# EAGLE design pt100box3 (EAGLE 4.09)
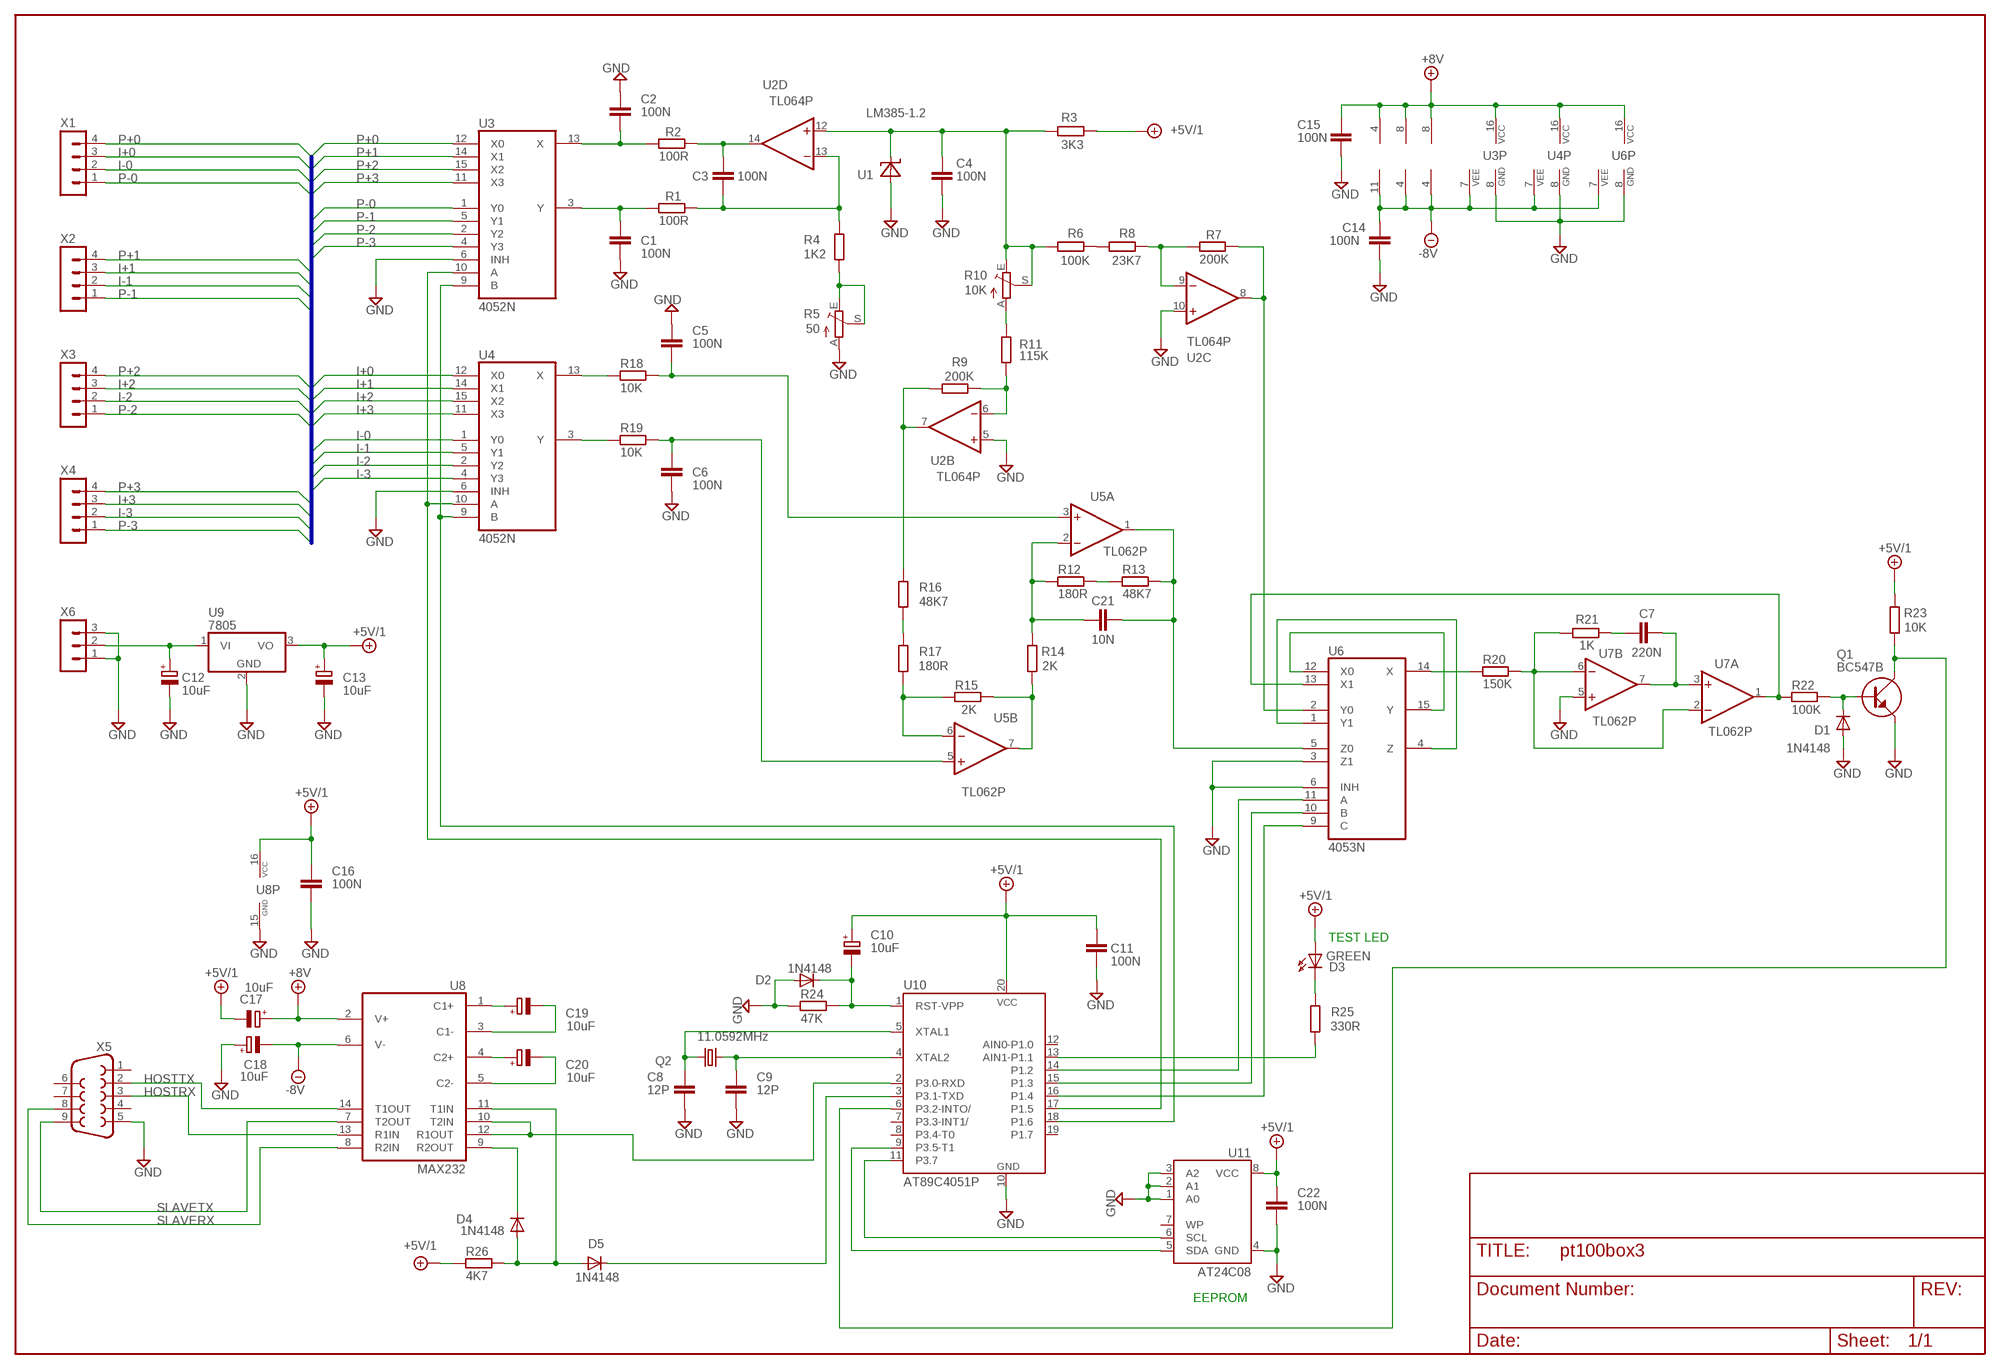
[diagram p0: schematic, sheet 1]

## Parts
C1  100N  NEWCC5  [C5]
C2  100N  NEWCC5  [C5]
C3  100N  NEWCC5  [C5]
C4  100N  NEWCC5  [C5]
C5  100N  NEWCC5  [C5]
C6  100N  NEWCC5  [C5]
C7  220N  C-EU102-064X133  [C102-064X133]
C8  12P  NEWCC2.5  [C2.5]
C9  12P  NEWCC2.5  [C2.5]
C10  10uF  CPOL-EUE2.5-6  [E2,5-6]
C11  100N  NEWCC5  [C5]
C12  10uF  CPOL-EUE2.5-6  [E2,5-6]
C13  10uF  CPOL-EUE2.5-6  [E2,5-6]
C14  100N  NEWCC5  [C5]
C15  100N  NEWCC5  [C5]
C16  100N  NEWCC5  [C5]
C17  10uF  CPOL-EUE2.5-6  [E2,5-6]
C18  10uF  CPOL-EUE2.5-6  [E2,5-6]
C19  10uF  CPOL-EUE2.5-6  [E2,5-6]
C20  10uF  CPOL-EUE2.5-6  [E2,5-6]
C21  10N  NEWCC2.5  [C2.5]
C22  100N  NEWC0805  [0805]
D1  1N4148  NEWDD7.5  [D7.5]
D2  1N4148  NEWDD7.5  [D7.5]
D3  GREEN  LED3MM  [LED3MM]
D4  1N4148  NEWDD7.5  [D7.5]
D5  1N4148  NEWDD7.5  [D7.5]
Q1  BC547B  NPNTO92  [TO92]
Q2  11.0592MHz  HC18U-V  [HC18U-V]
R1  100R  NEWRRM10  [RM10]
R2  100R  NEWRRM10  [RM10]
R3  3K3  NEWRRM10  [RM10]
R4  1K2  NEWRRM10  [RM10]
R5  50  TRIM_EU-S64Y  [S64Y]
R6  100K  NEWRRM10  [RM10]
R7  200K  NEWRRM10  [RM10]
R8  23K7  NEWRRM10  [RM10]
R9  200K  NEWRRM10  [RM10]
R10  10K  TRIM_EU-S64Y  [S64Y]
R11  115K  NEWRRM10  [RM10]
R12  180R  NEWRRM10  [RM10]
R13  48K7  NEWRRM10  [RM10]
R14  2K  NEWRRM10  [RM10]
R15  2K  NEWRRM10  [RM10]
R16  48K7  NEWRRM10  [RM10]
R17  180R  NEWRRM10  [RM10]
R18  10K  NEWRRM10  [RM10]
R19  10K  NEWRRM10  [RM10]
R20  150K  NEWRRM10  [RM10]
R21  1K  NEWRRM10  [RM10]
R22  100K  NEWRRM10  [RM10]
R23  10K  NEWRRM10  [RM10]
R24  47K  NEWRRM10  [RM10]
R25  330R  NEWRRM10  [RM10]
R26  4K7  NEWRRM10  [RM10]
U1  LM385-1.2  LM385TO  [TO92]
U2  TL064P  TL084P  [DIL14]
U3  4052N  [DIL16]
U4  4052N  [DIL16]
U5  TL062P  TL082P  [DIL08]
U6  4053N  [DIL16]
U7  TL062P  TL082P  [DIL08]
U8  MAX232  [DIL16]
U9  7805  78V  [TO220V]
U10  AT89C4051P  AT89C2051P  [DIL20]
U11  AT24C08  AT24CSO  [SOIC-8]
X1  MA04-1  [MA04-1]
X2  MA04-1  [MA04-1]
X3  MA04-1  [MA04-1]
X4  MA04-1  [MA04-1]
X5  F09H  [F09H]
X6  MA03-1  [MA03-1]

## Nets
+1.2: C4.2 R3.2 R6.2 R10.E R10.S U1.B(C) U2.12(D:+IN)
+5V/1: C10.+ C11.2 C13.+ C16.2 C17.- C22.2 D3.A R3.1 R23.2 R26.1 U8.16(VCC) U9.3(VO) U10.20(VCC) U11.8(VCC)
+8V: C15.2 C17.+ U2.4(P:V+) U3.16(VCC) U4.16(VCC) U5.8(P:V+) U6.16(VCC) U7.8(P:V+) U8.2(V+)
+12V: C12.+ U9.1(VI) X6.2
-2V: R7.2 U2.8(C:OUT) U6.2(Y0)
-8V: C14.2 C18.- U2.11(P:V-) U3.7(VEE) U4.7(VEE) U5.4(P:V-) U6.7(VEE) U7.4(P:V-) U8.6(V-)
-OFF: R9.2 R16.2 U2.7(B:OUT)
A: U6.11(A) U10.14(P1.2)
B: U6.10(B) U10.15(P1.3)
C: U6.9(C) U10.16(P1.4)
C1+: C19.+ U8.1(C1+)
C1-: C19.- U8.3(C1-)
C2+: C20.+ U8.4(C2+)
C2-: C20.- U8.5(C2-)
GND: C1.1 C2.2 C4.1 C5.2 C6.1 C8.1 C9.1 C11.1 C12.- C13.- C14.1 C15.1 C16.1 C18.+ C22.1 D1.A D2.A Q1.E R5.A R24.1 U1.E(A) U2.5(B:+IN) U2.10(C:+IN) U3.6(INH) U3.8(GND) U4.6(INH) U4.8(GND) U6.3(Z1) U6.6(INH) U6.8(GND) U7.5(B:+IN) U8.15(GND) U9.2(GND) U10.10(GND) U11.1(A0) U11.2(A1) U11.3(A2) U11.4(GND) X5.5 X6.1 X6.3
HOSTRX: U8.13(R1IN) X5.3
HOSTTX: U8.14(T1OUT) X5.2
I+0: U4.12(X0) X1.3
I+1: U4.14(X1) X2.3
I+2: U4.15(X2) X3.3
I+3: U4.11(X3) X4.3
I-0: U4.1(Y0) X1.2
I-1: U4.5(Y1) X2.2
I-2: U4.2(Y2) X3.2
I-3: U4.4(Y3) X4.2
INT0: Q1.C R23.1 U10.6(P3.2-INTO/)
LED1: R25.1 U10.13(AIN1-P1.1)
LED2: D3.K(C) R25.2
N$1: D4.C U8.9(R2OUT)
N$2: D4.A D5.A R26.2 U8.11(T1IN)
N$8: U10.9(P3.5-T1) U11.5(SDA)
N$9: U10.11(P3.7) U11.6(SCL)
P+0: U3.12(X0) X1.4
P+1: U3.14(X1) X2.4
P+2: U3.15(X2) X3.4
P+3: U3.11(X3) X4.4
P-0: U3.1(Y0) X1.1
P-1: U3.5(Y1) X2.1
P-2: U3.2(Y2) X3.1
P-3: U3.4(Y3) X4.1
Q1: C8.2 Q2.2 U10.5(XTAL1)
Q2: C9.2 Q2.1 U10.4(XTAL2)
RESET: C10.- D2.C R24.2 U10.1(RST-VPP)
RXD: U8.10(T2IN) U8.12(R1OUT) U10.2(P3.0-RXD)
SELA: U3.10(A) U4.10(A) U10.17(P1.5)
SELB: U3.9(B) U4.9(B) U10.18(P1.6)
SLAVERX: U8.8(R2IN) X5.8
SLAVETX: U8.7(T2OUT) X5.9
TXD: D5.C U10.3(P3.1-TXD)
X1: C2.1 R2.1 U3.13(X)
X2: C1.2 R1.1 U3.3(Y)
X3: C3.2 R2.2 U2.14(D:OUT)
X4: C3.1 R1.2 R4.2 U2.13(D:-IN)
X5: R4.1 R5.E R5.S
X6: R6.1 R8.2
X7: R7.1 R8.1 U2.9(C:-IN)
X8: R10.A R11.1
X9: R9.1 R11.2 U2.6(B:-IN)
X10: R18.1 U4.13(X)
X11: R19.1 U4.3(Y)
X12: C5.1 R18.2 U5.3(A:+IN)
X13: C6.2 R19.2 U5.5(B:+IN)
X14: R16.1 R17.2
X15: R15.1 R17.1 U5.6(B:-IN)
X16: R14.1 R15.2 U5.7(B:OUT)
X17: C21.2 R12.1 R14.2 U5.2(A:-IN)
X18: R12.2 R13.1
X19: C21.1 R13.2 U5.1(A:OUT) U6.5(Z0)
X20: R20.1 U6.14(X)
X21: R20.2 R21.1 U7.2(A:-IN) U7.6(B:-IN)
X22: C7.1 R21.2
X23: C7.2 U7.3(A:+IN) U7.7(B:OUT)
X24: R22.1 U6.13(X1) U7.1(A:OUT)
X25: D1.C Q1.B R22.2
X26: U6.1(Y1) U6.4(Z)
X27: U6.12(X0) U6.15(Y)
Unconnected: U2.1(A:OUT) U2.2(A:-IN) U2.3(A:+IN) U10.7(P3.3-INT1/) U10.8(P3.4-T0) U10.12(AIN0-P1.0) U10.19(P1.7) U11.7(WP) X5.1 X5.4 X5.6 X5.7

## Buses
P+[0..3],P-[0..3],I+[0..3],I-[0..3]

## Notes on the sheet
- TEST LED
- EEPROM

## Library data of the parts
C1-C6 C8 C9 C11 C14-C16 C21 C22 = NEWRC:NEWC
C7 = rcl:C-EU: CAPACITOR, European symbol
C10 C12 C13 C17-C20 = rcl:CPOL-EU: POLARIZED CAPACITOR, European symbol
D1 D2 D4 D5 = NEWRC:NEWD
D3 = led:LED3MM: LED
Q1 = NEWRC:NPN
Q2 = crystal:HC18U-V: CRYSTAL
R1-R4 R6-R9 R11-R26 = NEWRC:NEWR
R5 R10 = pot:TRIM_EU-: POTENTIOMETER
U1 = NEWRC:LM385
U2 = linear:TL084: OP AMP
U3 U4 = 40xx:4052: Dual 4-channel ANALOG MULTIPLEXER
U5 U7 = linear:TL082: OP AMP
U6 = 40xx:4053: Triple 2-channel ANALOG MULTIPLEXER
U8 = maxim:MAX232: RS232 TRANSEIVER
U9 = linear:78*: Positive VOLTAGE REGULATOR
U10 = atmel:AT89C2051: 80C31 MICROCONTROLLER 2 Kbytes FLASH 2.7 V
U11 = atmel:AT24C*: 2-wire serial EEPROM
X1-X4 = con-lstb:MA04-1: PIN HEADER
X5 = con-subd:F09: SUB-D
X6 = con-lstb:MA03-1: PIN HEADER

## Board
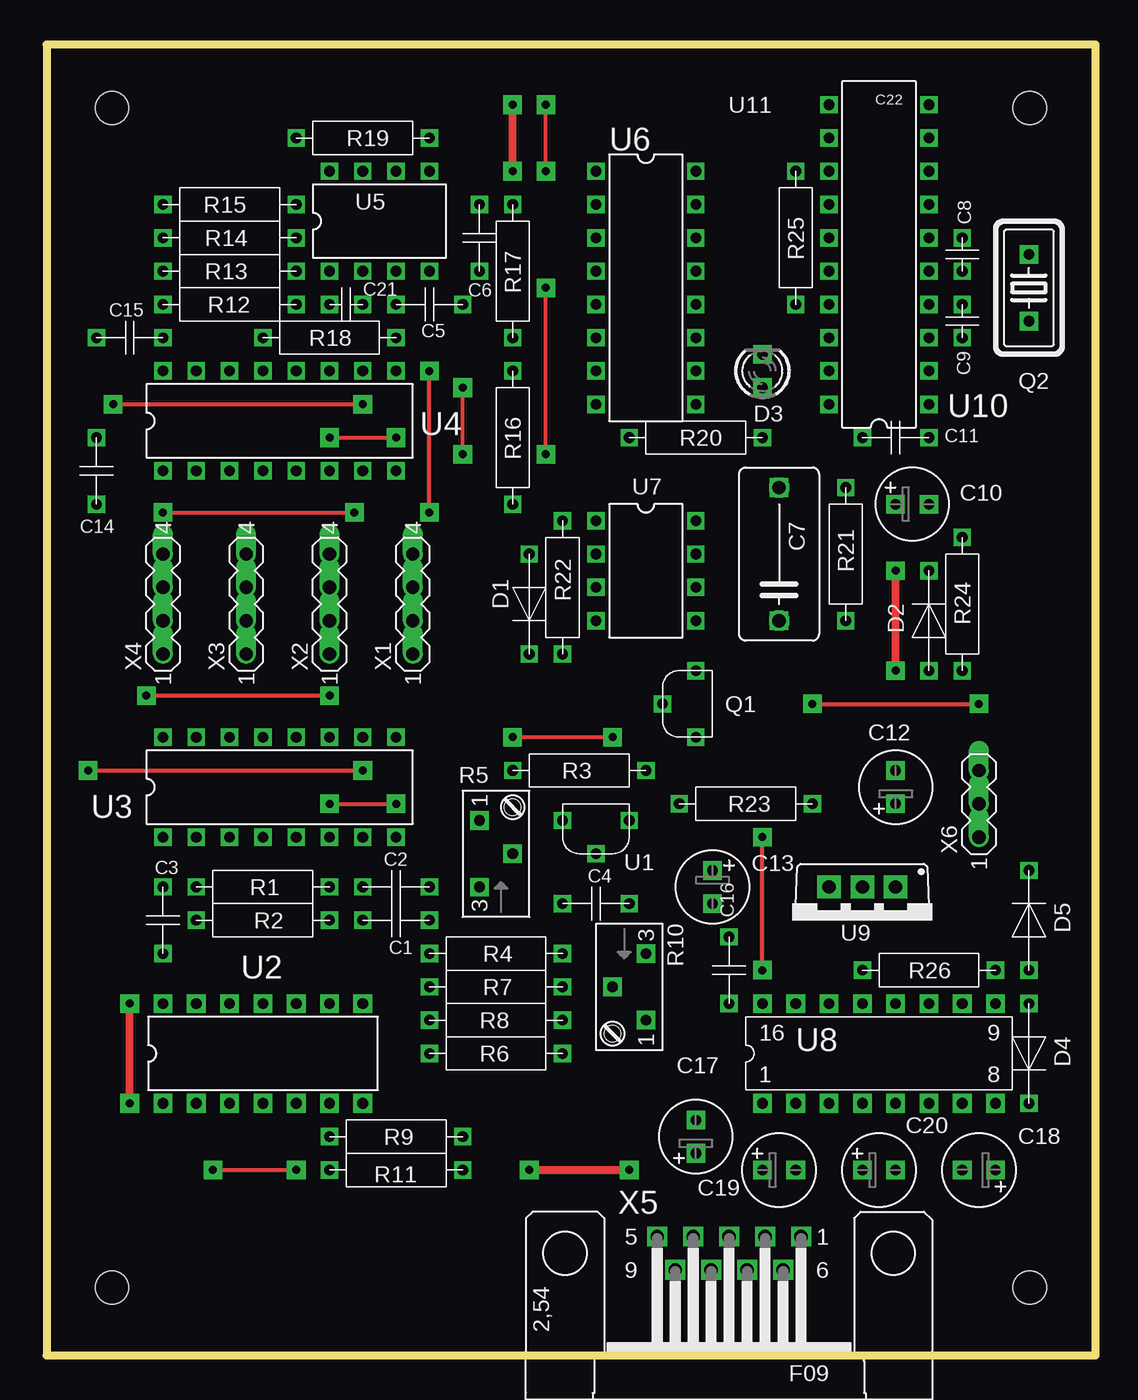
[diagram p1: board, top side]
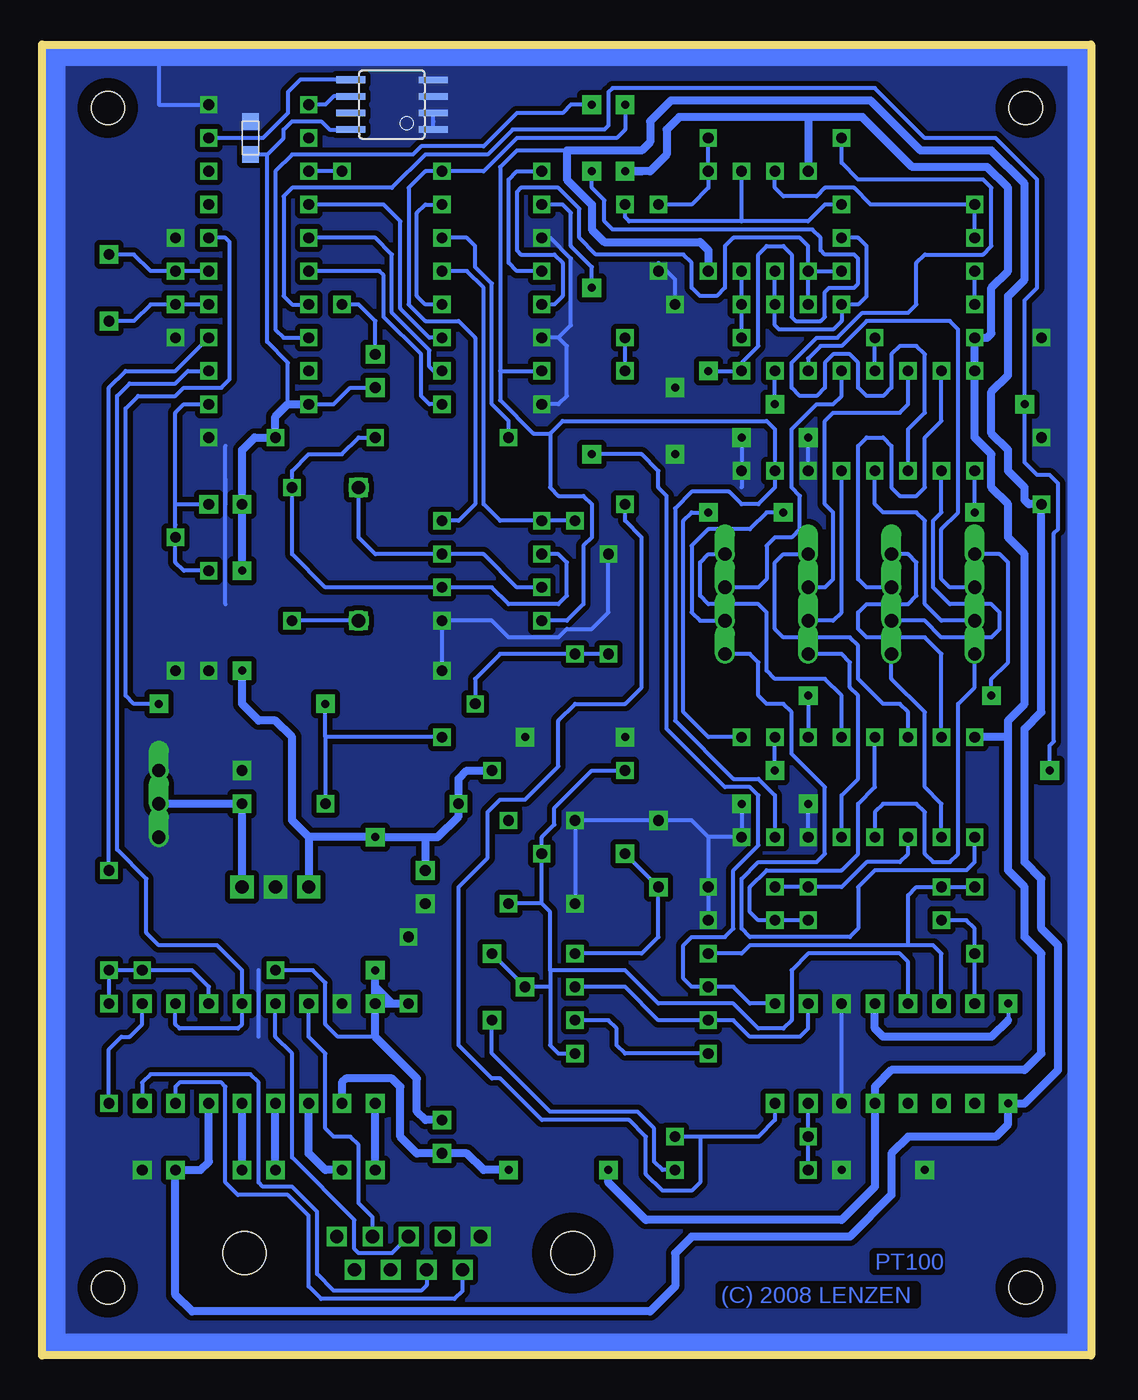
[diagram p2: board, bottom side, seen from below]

Size 80 x 100 mm. Coordinates in mm from the lower left corner, seen from the top.
Outline: 0,0 80,0 80,100 0,100 0,0
Copper layers used: Top, Bottom
Holes 2.54 mm at 4.98,95.17 74.98,95.17 74.98,5.17 4.98,5.17

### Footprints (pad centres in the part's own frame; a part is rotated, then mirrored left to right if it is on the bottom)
C5 = drill 0.813 pad 1.27 square: 1 0,0; 2 5.08,0
C102-064X133 = drill 1.016 octagon: 1 -5.08,0; 2 5.08,0
C2.5 = drill 0.813 pad 1.27 square: 1 0,0; 2 2.54,0
E2,5-6 = drill 0.813 pad 1.422 square: + -1.27,0; - 1.27,0
0805 = smd 1.27 x 1.27: 1 0,0; 2 2.54,0
D7.5 = drill 0.813 pad 1.27 square: A 0,0; C 7.62,0
LED3MM = drill 0.813 octagon: A -1.27,0; K 1.27,0
TO92 = drill 0.813 pad 1.27 square: B 0,0; C 2.54,-2.54; E 2.54,2.54
HC18U-V = drill 0.813 pad 1.422 square: 1 -2.54,0; 2 2.54,0
RM10 = drill 0.813 pad 1.27 square: 1 0,0; 2 10.16,0
S64Y = drill 0.813 pad 1.422 square: A 2.54,1.27; E -2.54,1.27; S 0,-1.27
DIL14 = drill 0.813 pad 1.422 square: 1 -7.62,-3.81; 2 -5.08,-3.81; 3 -2.54,-3.81; 4 0,-3.81; 5 2.54,-3.81; 6 5.08,-3.81; 7 7.62,-3.81; 8 7.62,3.81; 9 5.08,3.81; 10 2.54,3.81; 11 0,3.81; 12 -2.54,3.81; 13 -5.08,3.81; 14 -7.62,3.81
DIL16 = drill 0.813 square: 1 -8.89,-3.81; 2 -6.35,-3.81; 3 -3.81,-3.81; 4 -1.27,-3.81; 5 1.27,-3.81; 6 3.81,-3.81; 7 6.35,-3.81; 8 8.89,-3.81; 9 8.89,3.81; 10 6.35,3.81; 11 3.81,3.81; 12 1.27,3.81; 13 -1.27,3.81; 14 -3.81,3.81; 15 -6.35,3.81; 16 -8.89,3.81
DIL08 = drill 0.813 square: 1 -3.81,-3.81; 2 -1.27,-3.81; 3 1.27,-3.81; 4 3.81,-3.81; 5 3.81,3.81; 6 1.27,3.81; 7 -1.27,3.81; 8 -3.81,3.81
DIL16' = drill 0.813 pad 1.422 square: 1 -8.89,-3.81; 2 -6.35,-3.81; 3 -3.81,-3.81; 4 -1.27,-3.81; 5 1.27,-3.81; 6 3.81,-3.81; 7 6.35,-3.81; 8 8.89,-3.81; 9 8.89,3.81; 10 6.35,3.81; 11 3.81,3.81; 12 1.27,3.81; 13 -1.27,3.81; 14 -3.81,3.81; 15 -6.35,3.81; 16 -8.89,3.81
TO220V = drill 1.016 pad 1.778 square: 1 -2.54,0; 2 0,0; 3 2.54,0
DIL20 = drill 0.813 square: 1 -11.43,-3.81; 2 -8.89,-3.81; 3 -6.35,-3.81; 4 -3.81,-3.81; 5 -1.27,-3.81; 6 1.27,-3.81; 7 3.81,-3.81; 8 6.35,-3.81; 9 8.89,-3.81; 10 11.43,-3.81; 11 11.43,3.81; 12 8.89,3.81; 13 6.35,3.81; 14 3.81,3.81; 15 1.27,3.81; 16 -1.27,3.81; 17 -3.81,3.81; 18 -6.35,3.81; 19 -8.89,3.81; 20 -11.43,3.81
SOIC-8 = smd 0.5 x 2.2: 1 -1.905,-3.154; 2 -0.645,-3.154; 3 0.625,-3.154; 4 1.895,-3.154; 5 1.905,3.154; 6 0.635,3.154; 7 -0.635,3.154; 8 -1.905,3.154
MA04-1 = drill 1.016 offset: 1 -3.81,0; 2 -1.27,0; 3 1.27,0; 4 3.81,0
F09H = drill 1.016 pad 1.422 square: 1 -5.486,-1.27; 2 -2.743,-1.27; 3 0,-1.27; 4 2.743,-1.27; 5 5.486,-1.27; 6 -4.115,1.27; 7 -1.372,1.27; 8 1.372,1.27; 9 4.115,1.27 | hole 3.302: -12.522,0; 12.522,0
MA03-1 = drill 1.016 offset: 1 -2.54,0; 2 0,0; 3 2.54,0

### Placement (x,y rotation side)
C1  29.19,35.73 180 top
C2  24.11,33.19 0 top
C3  8.87,35.73 270 top
C4  39.35,34.46 0 top
C5  26.65,80.18 0 top
C6  33,82.72 90 top
C7  55.86,61.13 90 top
C8  69.83,85.26 270 top
C9  69.83,77.64 90 top
C10  66.02,64.94 0 top
C11  67.29,70.02 180 top
C12  64.75,43.35 90 top
C13  50.78,35.73 270 top
C14  3.79,70.02 270 top
C15  3.79,77.64 0 top
C16  52.05,31.92 270 top
C17  49.51,16.68 90 top
C18  71.1,14.14 180 top
C19  55.86,14.14 0 top
C20  63.48,14.14 0 top
C21  21.57,80.18 0 top
C22  64.11,94.15 270 bottom
D1  36.81,61.13 270 top
D2  67.29,52.24 90 top
D3  54.59,75.1 90 top
D4  74.91,26.84 270 top
D5  74.91,29.38 90 top
Q1  46.97,49.7 0 top
Q2  74.91,81.45 90 top
R1  21.57,35.73 180 top
R2  21.57,33.19 180 top
R3  45.7,44.62 180 top
R4  39.35,30.65 180 top
R5  34.27,38.27 90 top
R6  29.19,23.03 0 top
R7  39.35,28.11 180 top
R8  29.19,25.57 0 top
R9  21.57,16.68 0 top
R10  44.43,28.11 270 top
R11  31.73,14.14 180 top
R12  19.03,80.18 180 top
R13  8.87,82.72 0 top
R14  8.87,85.26 0 top
R15  19.03,87.8 180 top
R16  35.54,75.1 270 top
R17  35.54,87.8 270 top
R18  16.49,77.64 0 top
R19  19.03,92.88 0 top
R20  44.43,70.02 0 top
R21  60.94,66.21 270 top
R22  39.35,63.67 270 top
R23  58.4,42.08 180 top
R24  69.83,52.24 90 top
R25  57.13,90.34 270 top
R26  62.21,29.38 0 top
U1  41.89,38.27 90 top
U2  16.49,23.03 0 top
U3  17.76,43.35 0 top
U4  17.76,71.29 0 top
U5  25.38,86.53 0 top
U6  45.7,81.45 270 top
U7  45.7,59.86 270 top
U8  MAX232  [DIL16']  63.48,23.03 0 top
U9  62.21,35.73 180 top
U10  63.48,83.99 90 top
U11  53.32,95.42 90 bottom
X1  27.92,57.32 90 top
X2  21.57,57.32 90 top
X3  15.22,57.32 90 top
X4  8.87,57.32 90 top
X5  52.05,7.79 180 top
X6  71.1,42.08 90 top

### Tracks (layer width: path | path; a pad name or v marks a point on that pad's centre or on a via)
+1.2
  Bottom 0.305: R3.2 38.08,44.62 40.94,41.76 40.94,40.49 41.89,39.54 U1.B 41.89,34.46 | U2.12 13.95,30.02 14.58,30.65 21.57,30.65 22.84,29.38 22.84,25.57 23.47,24.94 25.38,24.94 27.28,26.84 33,26.84 35.54,29.38 41.25,29.38 | 41.25,29.38 41.25,33.83 41.89,34.46 | 41.89,34.46 C4.2 | 41.25,29.38 41.25,28.11 | 41.25,28.11 41.25,23.67 40.62,23.03 R6.2 | R10.E R10.S 41.25,28.11
+5V/1  (via drill 0.61 pad 1.42)
  Top 0.305: v54.59,29.38 v54.59,39.54
  Top 0.61: v64.75,52.24 v64.75,59.86
  Bottom 0.305: U10.20 57.76,72.56 56.49,73.83 D3.A | R26.1 59.35,29.38 58.4,28.43 58.4,25.25 57.45,24.3 54.59,24.3 | U11.8 58.08,93.52 58.71,94.15 60.94,94.15 61.57,93.52 61.57,92.88 62.84,91.61 | 62.84,91.61 62.84,77.32 61.26,75.73 61.26,72.56 | 62.84,91.61 C22.2
  Bottom 0.61: R3.1 47.6,44.62 48.24,43.98 R23.2 48.24,41.13 49.82,39.54 50.78,39.54 | U8.16 53.32,26.84 | 53.32,26.84 C16.2 | C17.- 50.78,17.95 51.41,18.59 51.41,21.12 54.59,24.3 U8.16 | v64.75,59.86 C10.+ 64.75,69.07 63.8,70.02 C11.2 62.21,71.61 61.26,72.56 U10.20 | v64.75,52.24 64.75,49.7 63.48,48.43 62.21,48.43 60.94,47.16 60.94,40.81 59.67,39.54 | 59.67,39.54 v54.59,39.54 50.78,39.54 | 59.67,39.54 U9.3 | 50.78,39.54 C13.+ | U8.16 54.59,28.11 | 54.59,28.11 v54.59,29.38 | 53.32,26.84 54.59,28.11
+8V  (via drill 0.61 pad 1.42)
  Top 0.61: v35.54,90.34 v35.54,95.42 | v36.81,14.14 v44.43,14.14
  Bottom 0.305: U7.8 48.24,63.67 46.97,64.94 46.97,77.64 48.24,78.91 50.78,78.91 52.05,80.18 52.05,89.07 50.78,90.34 U6.16 46.33,90.34 43.79,92.88 36.17,92.88 35.54,93.52 v35.54,95.42
  Bottom 0.61: 6.33,47.16 6.33,48.43 5.06,49.7 5.06,61.13 6.33,62.4 6.33,64.94 7.6,66.21 7.6,68.75 8.87,70.02 U4.16 C15.2 7.92,77.64 7.6,77.96 7.6,81.45 6.33,82.72 6.33,89.07 7.92,90.66 13.63,90.66 17.44,94.47 21.57,94.47 | 6.33,47.16 U3.16 | 6.33,47.16 6.33,37 5.06,35.73 5.06,31.92 3.79,30.65 3.79,23.03 5.06,21.76 15.22,21.76 16.49,20.49 U2.4 16.49,12.87 19.03,10.33 33.95,10.33 36.81,13.19 v36.81,14.14 | v35.54,90.34 33.63,90.34 32.36,91.61 32.36,93.52 31.41,94.47 21.57,94.47 | v35.54,90.34 35.22,90.34 | v35.54,90.34 34.27,90.34 | U8.2 57.13,20.81 56.81,21.12 53.32,21.12 52.68,20.49 52.68,16.68 51.41,15.41 C17.+ 47.6,15.41 46.33,14.14 v44.43,14.14 | 21.57,94.47 U5.8
+12V
  Bottom 0.61: X6.2 C12.+ U9.1
-2V  (via drill 0.61 pad 1.42)
  Top 0.305: v38.08,68.75 v38.08,81.45
  Bottom 0.305: U2.8 26.01,26.84 27.28,28.11 R7.2 30.46,28.11 31.09,28.75 31.09,31.29 30.46,31.92 27.92,31.92 27.28,32.55 27.28,37 25.38,38.91 25.38,42.72 26.01,43.35 27.92,43.35 32.36,47.8 32.36,65.58 33,66.21 33,67.48 34.27,68.75 v38.08,68.75 | v38.08,81.45 38.08,83.04 39.67,84.62 39.67,87.17 40.3,87.8 U6.2
-8V  (via drill 0.61 pad 1.42)
  Top 0.61: v6.33,19.22 v6.33,26.84
  Bottom 0.305: v6.33,26.84 6.33,25.57 | U3.7 24.11,42.72 25.38,43.98 27.28,43.98 31.73,48.43 31.73,64.62 30.46,65.89 27.6,65.89 26.65,64.94 25.38,64.94 24.11,66.21 U4.7 24.11,70.66 24.74,71.29 40.3,71.29 41.25,70.34 | 45.06,75.1 45.06,90.66 43.79,91.93 39.98,91.93 | 45.06,75.1 U6.7 | 45.06,75.1 45.06,72.88 42.52,70.34 41.25,70.34 | U7.4 39.98,56.05 38.71,57.32 38.71,61.77 38.08,62.4 38.08,64.94 38.71,65.58 40.62,65.58 41.25,66.21 41.25,70.34 | 6.33,18.9 6.33,19.54
  Bottom 0.61: U2.11 16.49,24.94 15.85,24.3 7.6,24.3 6.33,25.57 | v6.33,19.22 5.06,19.22 2.52,21.76 2.52,31.29 3.79,32.55 3.79,36.37 5.06,37.64 5.06,47.8 3.79,49.07 C14.2 4.74,64.94 5.06,65.26 5.06,66.21 6.33,67.48 6.33,69.07 7.6,70.34 7.6,73.51 6.33,74.78 6.33,80.81 5.06,82.09 5.06,89.39 7.6,91.93 13,91.93 16.81,95.74 32.05,95.74 33.63,94.15 33.63,92.56 34.27,91.93 39.98,91.93 39.98,89.7 38.08,87.8 38.08,85.89 37.13,84.94 29.82,84.94 29.19,84.31 U5.4 | U8.6 67.29,14.78 67.92,14.14 C18.- 69.83,4.62 68.56,3.34 33.63,3.34 31.73,5.25 31.73,7.79 30.46,9.06 18.39,9.06 15.22,12.23 15.22,15.41 13.95,16.68 7.28,16.68 6.33,17.63 6.33,18.9 v6.33,19.22 | v6.33,19.22 6.33,19.54
-OFF
  Bottom 0.305: U2.7 24.11,17.95 25.38,16.68 29.82,16.68 | 29.82,16.68 R9.2 | R16.2 35.54,63.67 34.27,62.4 34.27,50.97 35.54,49.7 39.35,49.7 40.62,48.43 40.62,44.94 43.16,42.4 45.06,42.4 46.02,41.45 46.02,37.95 48.24,35.73 48.24,23.67 45.7,21.12 45.06,21.12 41.89,17.95 35.22,17.95 33.95,16.68 33.95,13.82 32.68,12.55 30.46,12.55 29.82,13.19 29.82,16.68
A
  Bottom 0.305: U6.11 50.46,77.64 52.68,79.86 52.68,86.53 53.95,87.8 U10.14
B
  Bottom 0.305: U6.10 50.14,75.1 50.46,75.42 50.46,76.69 53.32,79.55 53.32,83.99 54.59,85.26 U10.15
C
  Bottom 0.305: U6.9 50.46,72.56 51.09,73.2 51.09,76.37 53.95,79.23 53.95,82.4 54.27,82.72 U10.16
C1+
  Bottom 0.61: C19.+ U8.1
C1-
  Bottom 0.61: C19.- 58.4,14.14 59.67,15.41 U8.3
C2+
  Bottom 0.61: C20.+ U8.4
C2-
  Bottom 0.61: C20.- U8.5
GND  (via drill 0.61 pad 1.42)
  Top 0.305: v21.57,70.02 v26.65,70.02 | v21.57,42.08 v26.65,42.08 | v31.73,68.75 v31.73,73.83 | v35.54,47.16 v43.16,47.16 | v12.68,14.14 v19.03,14.14
  Bottom 0.305: 29.19,39.54 30.46,40.81 R5.A U1.E C4.1 | 29.19,39.54 C1.1 C2.2 | U2.5 U2.10 | C6.1 33,83.36 31.73,82.09 C5.2 | 26.65,66.21 U4.8 v26.65,70.02 | 29.19,39.54 U3.8 v26.65,42.08 | Q1.E U7.5 45.7,56.05 44.43,54.78 40.62,54.78 39.98,55.41 38.08,55.41 36.81,56.69 D1.A | U6.8 40.62,72.56 39.98,73.2 39.98,77 40.62,77.64 | U4.6 v21.57,70.02 | U3.6 v21.57,42.08 | 66.02,66.84 66.02,64.94 | 66.02,66.84 66.02,69.39 | 63.48,24.3 63.48,29.38 | 66.02,57.32 66.02,66.84 | U6.3 41.25,85.26 39.67,83.67 39.67,78.59 40.62,77.64 | 40.62,77.64 U6.6 | U10.10 71.1,95.42 71.1,99.23 | 50.15,94.14 50.14,94.15 | 50.15,94.14 U11.2 | U11.1 50.16,94.13 50.15,94.14
  Bottom 1.676: 0.61,99.23 71.1,99.23 79.04,99.23 79.04,0.81 0.93,0.81 0.93,98.91
  pour Bottom (isolate 0.406, no thermals): 1.25,99.23 78.72,99.23 78.72,1.44 1.25,1.44
HOSTRX
  Bottom 0.305: U8.13 62.21,24.3 60.94,23.03 60.94,15.09 56.17,10.33 56.17,8.11 55.86,7.79 53.32,7.79 X5.3
HOSTTX
  Bottom 0.305: U8.14 59.67,24.3 58.4,23.03 58.4,17.32 57.76,16.68 56.49,16.68 55.86,16.05 55.86,11.6 54.79,10.53 X5.2
I+0
  Bottom 0.305: X1.3 25.38,58.59 24.74,59.23 24.74,61.77 24.11,62.4 22.84,62.4 22.2,63.04 22.2,65.58 22.84,66.21 22.84,70.66 20.93,72.56 19.66,72.56 19.03,73.2 U4.12
I+1
  Bottom 0.305: X2.3 20.3,58.59 19.66,59.23 19.66,64.31 20.3,64.94 20.3,71.29 19.66,71.92 14.58,71.92 13.95,72.56 U4.14
I+2
  Bottom 0.305: X3.3 17.12,58.59 17.76,59.23 17.76,69.39 17.12,70.02 15.85,70.02 15.22,69.39 15.22,66.21 14.58,65.58 13.31,65.58 12.68,66.21 12.68,70.02 11.41,71.29 U4.15
I+3
  Bottom 0.305: X4.3 10.77,58.59 11.41,59.23 11.41,63.04 10.14,64.31 10.14,78.28 10.77,78.91 17.12,78.91 19.03,77 20.61,77 21.57,76.05 U4.11
I-0  (via drill 0.61 pad 1.42)
  Top 0.305: v8.87,64.31 v23.47,64.31
  Bottom 0.305: v8.87,64.31 U4.1 | v23.47,64.31 24.74,64.31 26.01,63.04 29.19,63.04 30.46,61.77 30.46,56.69 29.82,56.05 X1.2
I-1
  Bottom 0.305: U4.5 19.03,56.69 19.66,56.05 X2.2
I-2
  Bottom 0.305: X3.2 12.68,56.05 11.41,54.78 7.6,54.78 6.96,55.41 6.96,56.69 7.6,57.32 10.77,57.32 12.04,58.59 12.04,63.67 11.41,64.31 U4.2
I-3
  Bottom 0.305: X4.2 11.41,56.05 12.68,57.32 12.68,63.67 13.31,64.31 15.85,64.31 16.49,64.94 U4.4
INT0  (via drill 0.61 pad 1.42)
  Top 0.305: v58.4,49.7 v71.1,49.7
  Bottom 0.305: Q1.C 58.4,47.16 | U10.6 66.02,85.26 65.7,84.94 65.7,74.47 66.34,73.83 69.19,73.83 69.83,73.2 72.68,73.2 73.64,72.24 73.64,50.34 73,49.7 v71.1,49.7 | 58.4,47.16 R23.1 | 58.4,47.16 v58.4,49.7
LED1
  Bottom 0.305: R25.1 U10.13
LED2
  Bottom 0.305: D3.K 54.59,78.91 55.86,80.18 R25.2
N$1
  Bottom 0.305: U8.9 72.37,25.25 73.32,24.3 73.96,24.3 74.91,23.35 D4.C
N$2
  Bottom 0.305: U8.11 67.29,28.11 68.56,29.38 R26.2 | R26.2 D5.A | D5.A D4.A | R26.2 D5.A
N$8
  Bottom 0.305: U11.5 60.3,97.33 61.26,96.37 61.26,94.78 63.16,92.88 U10.9
N$9
  Bottom 0.305: U11.6 57.76,96.06 58.4,95.42 U10.11
N$46  (via drill 0.61 pad 0.81)
  other vias: 4.98,95.17
N$47  (via drill 0.61 pad 0.81)
  other vias: 74.98,95.17
N$50  (via drill 0.61 pad 0.81)
  other vias: 74.98,5.17
N$51  (via drill 0.61 pad 0.81)
  other vias: 4.98,5.17
N$53  (via drill 0.61 pad 1.42)
  other vias: 55.86,56.05
N$54  (via drill 0.61 pad 1.42)
  other vias: 55.86,66.21
N$55  (via drill 0.61 pad 1.42)
  other vias: 54.59,73.83
N$56  (via drill 0.61 pad 1.42)
  other vias: 54.59,76.37
P+0
  Bottom 0.305: U3.12 19.03,50.34 20.3,51.61 24.11,51.61 24.74,52.24 24.74,56.69 25.38,57.32 29.19,57.32 29.82,57.95 29.82,60.5 29.19,61.13 X1.4
P+1
  Bottom 0.305: U3.14 13.95,49.07 14.58,49.7 15.85,49.7 17.76,51.61 17.76,54.15 18.39,54.78 23.47,54.78 24.11,55.41 24.11,60.5 23.47,61.13 X2.4
P+2
  Bottom 0.305: U3.15 11.41,53.51 12.68,54.78 17.12,54.78 17.76,55.41 17.76,56.69 17.12,57.32 13.95,57.32 13.31,57.95 13.31,60.5 13.95,61.13 X3.4
P+3  (via drill 0.61 pad 1.42)
  Top 0.305: v7.6,50.34 v21.57,50.34
  Bottom 0.305: X4.4 6.96,61.13 6.33,60.5 6.33,52.88 7.6,51.61 v7.6,50.34 | v21.57,50.34 U3.11
P-0
  Bottom 0.305: U3.1 8.87,37.64 9.5,37 16.49,37 17.76,35.73 17.76,32.55 18.39,31.92 26.01,31.92 26.65,32.55 26.65,36.37 25.38,37.64 20.93,37.64 20.3,38.27 20.3,43.35 22.84,45.89 22.84,49.07 23.47,49.7 24.74,49.7 25.38,50.34 25.38,52.88 26.01,53.51 X1.1
P-1
  Bottom 0.305: X2.1 19.03,53.51 18.39,52.88 18.39,50.97 17.76,50.34 17.76,43.98 19.03,42.72 U3.5
P-2
  Bottom 0.305: X3.1 15.22,51.61 12.68,49.07 12.68,43.35 11.41,42.08 U3.2
P-3
  Bottom 0.305: X4.1 8.87,50.97 10.14,49.7 10.14,38.27 10.77,37.64 12.04,37.64 12.68,38.27 12.68,41.45 13.31,42.08 15.85,42.08 16.49,41.45 U3.4
Q1
  Bottom 0.305: U10.5 C8.2 71.73,82.72 73,83.99 Q2.2
Q2
  Bottom 0.305: U10.4 C9.2 71.73,80.18 73,78.91 Q2.1
RESET
  Bottom 0.305: U10.1 69.19,72.56 69.83,71.92 69.83,64.94 | R24.2 69.83,64.94 | R24.2 69.83,63.35 | 69.83,64.94 C10.- | D2.C 69.19,59.86 69.83,60.5 R24.2
RXD
  Bottom 0.305: U10.2 68.87,75.1 69.83,74.15 73.32,74.15 74.27,73.2 74.27,38.59 72.05,36.37 72.05,32.24 71.1,31.29 66.65,31.29 64.75,29.38 U8.12 64.75,25.25 65.07,24.94 69.51,24.94 69.83,25.25 U8.10
SELA  (via drill 0.61 pad 1.42)
  Top 0.305: v5.06,72.56 v24.11,72.56 | v3.15,44.62 v24.11,44.62
  Bottom 0.305: U10.17 60.94,80.18 61.57,80.81 61.57,88.44 60.94,89.07 53.32,89.07 50.78,91.61 46.02,91.61 44.11,93.52 37.13,93.52 36.81,93.83 36.81,96.37 36.49,96.69 16.49,96.69 12.68,92.88 7.28,92.88 4.11,89.7 4.11,81.45 5.06,80.5 v5.06,72.56 5.06,68.11 4.11,67.16 3.15,67.16 2.52,66.53 2.52,63.04 2.83,62.72 2.83,46.84 3.15,46.52 v3.15,44.62 | v24.11,72.56 U4.10 | v24.11,44.62 U3.10
SELB  (via drill 0.61 pad 1.42)
  Top 0.305: v38.08,90.34 v38.08,95.42 | v29.19,64.31 v29.19,75.1
  Bottom 0.305: v38.08,95.42 39.67,95.42 40.3,94.78 43.79,94.78 46.33,92.25 51.09,92.25 51.73,91.61 60.94,91.61 62.21,90.34 62.21,78.28 61.57,77.64 U10.18 | v29.19,75.1 U4.9 26.65,75.73 25.38,77 25.38,83.99 24.74,84.62 23.47,84.62 22.84,83.99 22.84,79.23 22.52,78.91 20.61,78.91 20.3,79.23 20.3,81.13 19.98,81.45 18.08,81.45 17.76,81.77 17.76,83.67 18.08,83.99 20.3,83.99 20.61,84.31 20.61,85.26 21.25,85.89 36.49,85.89 37.13,86.53 37.13,88.12 38.08,89.07 v38.08,90.34 | U3.9 29.19,47.16 31.09,49.07 31.09,63.67 30.46,64.31 v29.19,64.31
SLAVERX
  Bottom 0.305: X5.8 50.68,5.35 51.09,4.93 57.76,4.93 59.03,6.2 59.03,10.96 60.94,12.87 63.16,12.87 63.48,13.19 63.48,20.81 64.11,21.44 71.73,21.44 72.37,20.81 U8.8
SLAVETX
  Bottom 0.305: X5.9 47.93,4.92 48.56,4.3 58.71,4.3 59.67,5.25 59.67,10.65 61.26,12.23 65.07,12.23 66.02,13.19 66.02,20.49 66.34,20.81 69.51,20.81 69.83,20.49 U8.7
TXD
  Bottom 0.305: U10.3 69.83,75.1 73.64,75.1 74.91,73.83 D5.C
X1
  Bottom 0.305: R2.1 C2.1 25.38,33.19 26.01,33.83 26.01,35.73 24.74,37 19.03,37 17.76,38.27 17.76,42.08 16.49,43.35 U3.13
X2
  Bottom 0.305: U3.3 13.95,38.27 14.58,37.64 17.12,37.64 19.03,35.73 R1.1 C1.2
X3
  Bottom 0.305: R2.2 9.5,33.19 8.87,32.55 C3.2 U2.14
X4
  Bottom 0.305: U2.13 11.41,30.65 12.04,31.29 13.95,31.29 | 13.95,31.29 13.95,35.09 13.31,35.73 R1.2 C3.1 | R4.2 26.65,30.65 26.01,31.29 13.95,31.29
X5
  Bottom 0.305: R5.S R5.E 33,31.92 34.27,30.65 R4.1
X6
  Bottom 0.305: R6.1 35.54,23.03 36.17,23.67 36.17,24.94 36.81,25.57 R8.2
X7
  Bottom 0.305: R7.1 35.54,28.11 33,25.57 R8.1 27.28,25.57 26.01,24.3 22.2,24.3 21.57,24.94 U2.9
X8
  Bottom 0.305: R10.A 45.7,23.03 41.25,18.59 34.59,18.59 33.31,17.32 33.31,14.78 32.68,14.14 R11.1
X9
  Bottom 0.305: U2.6 R9.1 R11.2
X10
  Bottom 0.305: U4.13 R18.1
X11
  Bottom 0.305: U4.3 13.95,70.66 12.68,71.92 12.68,76.37 13.31,77 14.58,77 15.22,76.37 15.22,73.83 15.85,73.2 17.12,73.2 17.76,73.83 17.76,75.73 18.39,76.37 19.66,76.37 20.3,75.73 20.3,73.83 20.93,73.2 22.2,73.2 22.84,73.83 22.84,75.73 20.93,77.64 19.34,77.64 17.44,79.55 13.95,79.55 13.31,80.18 13.31,83.36 12.68,83.99 8.23,83.99 7.6,84.62 7.6,89.07 8.23,89.7 17.76,89.7 19.03,90.98 R19.1
X12
  Bottom 0.305: U5.3 R18.2 C5.1
X13
  Bottom 0.305: C6.2 30.46,87.8 29.19,89.07 U5.5 R19.2
X14
  Bottom 0.305: R16.1 R17.2
X15
  Bottom 0.305: R15.1 20.3,87.8 21.57,86.53 26.65,86.53 | 26.65,86.53 U5.6 | 26.65,86.53 35.22,86.53 35.54,86.85 R17.1
X16
  Bottom 0.305: R14.1 R15.2 16.81,87.8 18.08,89.07 20.3,89.07 20.93,88.44 23.47,88.44 24.11,89.07 U5.7
X17
  Bottom 0.305: R12.1 19.03,80.5 | R12.1 19.03,78.91 19.66,78.28 23.79,78.28 24.11,78.59 C21.2 U5.2 | R14.2 17.76,85.26 17.12,84.62 17.12,80.81 17.76,80.18 R12.1
X18
  Bottom 0.305: R12.2 R13.1
X19
  Bottom 0.305: U5.1 R13.2 | U5.1 21.57,84.62 22.2,85.26 27.28,85.26 27.92,84.62 27.92,81.45 28.55,80.81 29.82,80.81 30.46,81.45 30.46,83.36 31.09,83.99 37.76,83.99 39.03,85.26 39.03,87.48 40.62,89.07 43.48,89.07 43.79,88.75 43.79,84.31 43.48,83.99 40.94,83.99 40.3,83.36 40.3,80.81 40.94,80.18 U6.5 | C21.1 U5.1
X20
  Bottom 0.305: R20.1 44.43,71.29 45.7,72.56 45.7,81.77 46.97,83.04 46.97,84.62 47.6,85.26 U6.14
X21
  Bottom 0.305: U7.2 40.62,61.13 39.98,60.5 39.98,57.95 40.62,57.32 44.43,57.32 45.7,58.59 U7.6 58.4,58.59 60.94,61.13 R21.1 60.94,67.48 59.67,68.75 57.13,68.75 55.86,70.02 R20.2
X22
  Bottom 0.305: C7.1 R21.2
X23
  Bottom 0.305: C7.2 55.86,62.4 54.59,61.13 U7.7 46.33,61.13 43.79,58.59 U7.3
X24
  Bottom 0.305: U6.13 47.6,82.72 46.33,81.45 46.33,64.94 45.06,63.67 U7.1 R22.1
X25
  Bottom 0.305: Q1.B 46.97,51.61 45.06,53.51 R22.2 D1.C
X26
  Bottom 0.305: U6.4 43.79,82.72 44.43,83.36 44.43,89.7 43.79,90.34 U6.1
X27
  Bottom 0.305: U6.12 50.78,80.18 51.41,80.81 51.41,87.17 50.78,87.8 U6.15

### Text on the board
Bottom: PT100 | (C) 2008 LENZEN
